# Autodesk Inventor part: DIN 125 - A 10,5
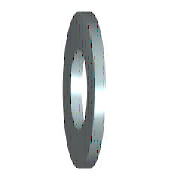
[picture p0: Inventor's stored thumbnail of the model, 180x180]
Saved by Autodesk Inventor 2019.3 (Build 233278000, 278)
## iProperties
Created: 2018-01
Part Number: DIN 125 - A 10,5
Material: Ocel, měkká
Description: Podložka
Document SubType Name: Modeling
Standard: DIN 125
Designer: B-hon
Standards Organization: DIN
Language: cs-CZ
Size Designation: A 10,5
Categories: <MemberInstance><Categories><Category DisplayName="Spojovací materiál" InternalName="e4da775c-781d-43d5-af7c-5136215cf5a6" Mnemonic="FSTN"><Category DisplayName
Density: 7.85 g/cm^3
Appearance: Pololeštěná
IsCustomPart: 0
Author: B-hon
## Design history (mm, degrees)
sketch "Náčrt"
  geometry: C1 r 10 at (0, 0); C2 r 5.25 at (0, 0); 1 further point
  constraints: 2 centre point, 2 coincident
  dimensions: "d0" = 10.5 diameter of C2 (= SD1); "d1" = 20 diameter of C1 (= SD2)
extrude "Těleso" new body sketch "Náčrt" distance "d2" = 2 (= SD); taper "d3" = 0 deg
workaxis "Work Axis1"
workplane "Work Plane1"
body "Solid1"
other parameters: "SD1" = 10.5 [user parameter; used in 1 equation term], "SD2" = 20 [user parameter; used in 1 equation term], "SD" = 2 [user parameter; used in 1 equation term], "d4" = 0, "d5" = 0, "d6" = 0, "d7" = 0
